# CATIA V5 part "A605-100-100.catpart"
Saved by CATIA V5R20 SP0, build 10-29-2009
Part number: A605-100-100
Source: Unknown
Property "A": "70.000"
Property "ARTICLENO": "A605-100-100"
Property "BOMINFO": "A605-100-100"
Property "CODE": "A605-100-100"
Property "D": "9.000"
Property "FORM": "C"
Property "L": "100.000"
Property "L1": "70.000"
Property "LINA": "A605-100-100"
Property "NB": "A605-100-100"
Property "NBSYN": "$CODE."
Property "NN": "A605"
Property "NT": "Wear Plates, self-lubricating"
Property "SCREW": "4*M8X16"
Property "SUPPLIER": "CF"
Property "W": "100.000"
Bounding box of the stored display mesh (mm): x -100 to 0, y 0 to 5, z -100 to 0
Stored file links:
  C:\Users\Utente\Desktop\3D files A605\A605-100-100.catpart
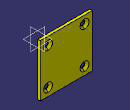
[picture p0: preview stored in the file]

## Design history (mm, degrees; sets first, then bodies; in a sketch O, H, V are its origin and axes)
Body1 "Geometry.1" (main body)
  Solid1 "A605-100-100.catpart": solid without history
